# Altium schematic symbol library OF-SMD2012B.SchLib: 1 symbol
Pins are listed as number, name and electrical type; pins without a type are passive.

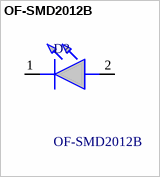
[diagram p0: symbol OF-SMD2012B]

## OF-SMD2012B
designator D?
LED; SMD; 0805; blue; 150200mcd; 2x1.25x0.68mm; 120; 33.2V; 20mA; Manufacturer_Name: OPTOFLASH; Geometry.Height: 0.88mm
footprint OFSMD2012B
pins: 1 K, 2 A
